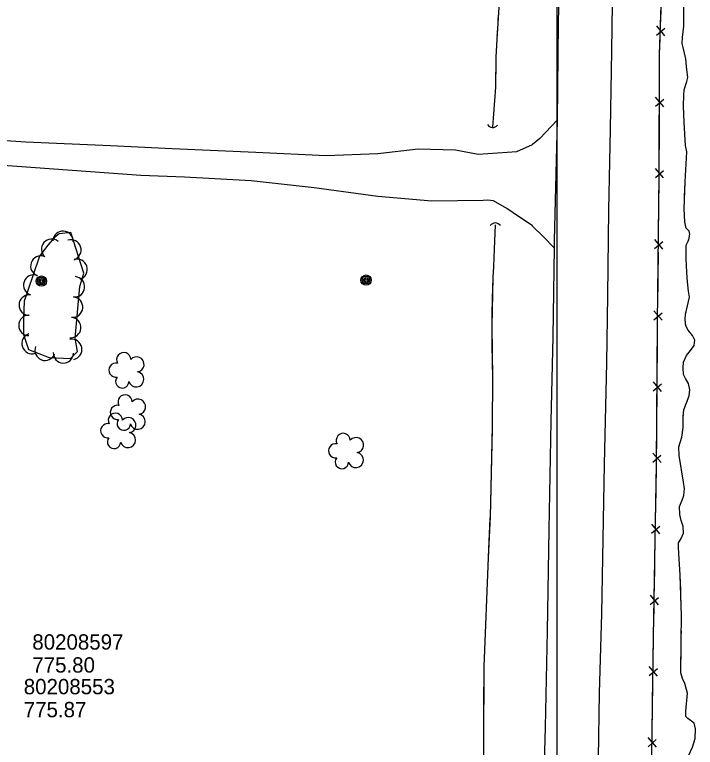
# Model space of a CAD drawing. Extents: x 591954 to 597000, y 198576 to 213500.
# Drawn here: x 593787.5 to 594054.2, y 209035.1 to 209321.9 of the extents above; entities that cross this region are included whole.
import ezdxf

# ---------------------------------------------------------------- set-up
doc = ezdxf.new("R2010")
doc.units = 0
for name, color, linetype in [('Level 10', 7, 'Continuous'), ('Level 11', 7, 'Continuous'), ('Level 14', 7, 'Continuous'), ('Level 15', 7, 'Continuous'), ('Level 17', 7, 'Continuous'), ('Level 18', 7, 'Continuous'), ('Level 19', 7, 'Continuous'), ('Level 6', 7, 'Continuous')]:
    doc.layers.add(name, color=color, linetype=linetype)

msp = doc.modelspace()

# ---------------------------------------------------------------- linework, layer by layer
at = {"layer": 'Level 10'}
msp.add_line((594000, 208500), (594000, 210000), dxfattribs=at)
at = {"layer": 'Level 11'}
for points in [[(594020.92, 209277.11), (594021.48, 209307.69), (594021.88, 209335.45), (594022.61, 209371.28), (594023.09, 209403.36), (594023.94, 209439.53), (594024.67, 209469.56), (594025.38, 209501.65), (594026.16, 209533.36), (594026.37, 209550.34)], [(594004.19, 209515.2), (594003.26, 209463.8), (594002.68, 209437.72), (594002.04, 209402.73), (594001.04, 209348.37), (594000.39, 209318.67), (593999.97, 209280.6)], [(593999.97, 209280.6), (593998.9, 209233.41), (593998.85, 209230.64)], [(594009.01, 208631.52), (594009.27, 208667.78), (594010.66, 208721.83), (594011.4, 208782.36), (594012.13, 208808.26), (594012.62, 208840.15), (594013.04, 208868.19), (594013.68, 208893.39), (594014.42, 208925.71), (594015, 208950.25), (594015.72, 209004.45), (594016.24, 209030.86), (594016.62, 209056.33), (594017.53, 209087.3), (594018.52, 209145.92), (594019.42, 209185.52), (594019.83, 209212.01), (594020.29, 209245.3), (594020.92, 209277.11)], [(593998.85, 209230.64), (593998.3, 209195.94), (593997.61, 209162.68), (593996.73, 209120.37), (593996.08, 209080.6), (593995.31, 209042.89), (593994.35, 209005.26), (593994.1, 208967.53), (593993.55, 208932.78), (593992.64, 208890.84), (593992, 208857.63), (593991.15, 208818.04), (593990.48, 208781.03), (593989.3, 208741.66), (593988.74, 208713.42), (593988.39, 208682.48), (593987.81, 208648.94), (593987.57, 208630.06)]]:
    msp.add_lwpolyline(points, dxfattribs=at)
at = {"layer": 'Level 14'}
for centre, radius in [((593925.18, 209217.97), 2.02), ((593798.02, 209217.58), 2.02), ((593798.01, 209217.6), 1.52), ((593798.02, 209217.56), 1.01), ((593798.02, 209217.57), 0.502), ((593925.18, 209217.99), 1.52), ((593925.18, 209217.95), 1.01), ((593925.19, 209217.96), 0.502)]:
    msp.add_circle(centre, radius, dxfattribs=at)
at = {"layer": 'Level 15'}
for p, q in [((594038.92, 209313.91), (594042.18, 209316.6)), ((594042.15, 209313.64), (594039.03, 209317.46)), ((594041.83, 209285.83), (594038.61, 209289.56)), ((594038.6, 209286.01), (594041.78, 209288.8)), ((594038.49, 209258.15), (594041.68, 209260.93)), ((594041.73, 209257.97), (594038.51, 209261.7)), ((594038.2, 209230.3), (594041.4, 209233.07)), ((594041.43, 209230.1), (594038.23, 209233.85)), ((594041.14, 209202.24), (594037.94, 209205.99)), ((594037.9, 209202.45), (594041.1, 209205.21)), ((594037.69, 209174.58), (594040.88, 209177.35)), ((594040.92, 209174.39), (594037.71, 209178.13)), ((594037.47, 209146.72), (594040.67, 209149.49)), ((594040.71, 209146.53), (594037.5, 209150.27)), ((594036.99, 209118.88), (594040.21, 209121.62)), ((594040.23, 209118.65), (594037.05, 209122.43)), ((594036.5, 209091.03), (594039.72, 209093.77)), ((594039.74, 209090.8), (594036.56, 209094.57)), ((594036.06, 209063.16), (594039.27, 209065.91)), ((594039.29, 209062.95), (594036.11, 209066.71)), ((594035.65, 209035.31), (594038.86, 209038.06)), ((594038.89, 209035.09), (594035.7, 209038.86))]:
    msp.add_line(p, q, dxfattribs=at)
for points in [[(594030.79, 208634.01), (594031.94, 208683.98), (594033.37, 208764.41), (594034.53, 208848.11), (594035.64, 208920.32), (594036.5, 208979.5), (594037.1, 209031.73), (594037.78, 209078.39), (594038.97, 209145.83), (594039.39, 209201.19), (594040, 209259.04), (594040.17, 209306.37), (594041.42, 209344.67), (594041.5, 209389.61), (594042.2, 209438.38), (594043.44, 209486.71), (594045.27, 209558.54)], [(594040.59, 209319.11), (594040.96, 209330.43)], [(594040.16, 209302.58), (594040.17, 209306.37), (594040.37, 209312.53)], [(594040.12, 209291.26), (594040.16, 209302.58)], [(594040.06, 209274.72), (594040.09, 209284.68)], [(594040.01, 209263.4), (594040.06, 209274.72)], [(594039.87, 209246.86), (594039.97, 209256.82)], [(594039.75, 209235.54), (594039.87, 209246.86)], [(594039.58, 209219), (594039.68, 209228.96)], [(594039.46, 209207.68), (594039.58, 209219)], [(594039.31, 209191.14), (594039.39, 209201.1)], [(594039.23, 209179.82), (594039.31, 209191.14)], [(594039.1, 209163.28), (594039.18, 209173.24)], [(594039.01, 209151.96), (594039.1, 209163.28)], [(594038.78, 209135.43), (594038.96, 209145.38)], [(594038.58, 209124.11), (594038.78, 209135.43)], [(594038.29, 209107.57), (594038.47, 209117.52)], [(594038.09, 209096.25), (594038.29, 209107.57)], [(594037.8, 209079.71), (594037.98, 209089.67)], [(594037.63, 209068.39), (594037.78, 209078.39), (594037.8, 209079.71)], [(594037.39, 209051.86), (594037.54, 209061.81)], [(594037.23, 209040.54), (594037.39, 209051.86)]]:
    msp.add_lwpolyline(points, dxfattribs=at)
for centre, start, end in [((593974.76, 209280.23), 214.2082, 320.4478), ((593975.78, 209237.83), 36.8794, 143.119)]:
    msp.add_arc(centre, 2.5, start, end, dxfattribs=at)
at = {"layer": 'Level 17'}
for points in [[(593549.62, 209275.76), (593550.25, 209275.98), (593557.81, 209277.99), (593569.7, 209280.1), (593588.61, 209280.91), (593618.58, 209281.04), (593645.5, 209280.53), (593677.34, 209278.92), (593706.45, 209277.89), (593735.5, 209275.73), (593764.6, 209273.9), (593791.92, 209272.11), (593825.06, 209270.71), (593849.21, 209269.45), (593881.95, 209268.09), (593909.58, 209266.77), (593929.73, 209267.52), (593945.57, 209269.4), (593960.22, 209268.99), (593969.04, 209267.32), (593984.2, 209268.32), (593990.43, 209271.07)], [(593999.97, 209280.61), (593993.2, 209273.43), (593990.43, 209271.07)], [(593990.32, 209239.2), (593982.82, 209244.3), (593980.33, 209246.04), (593975.05, 209249.06), (593972.79, 209249.31), (593971.01, 209249.16), (593950.93, 209248.82), (593929.84, 209250.72), (593904.86, 209254.13), (593880.15, 209256.85), (593854.02, 209258.32), (593836.93, 209258.94), (593781.28, 209262.91)], [(593990.24, 209239.26), (593994.74, 209234.86), (593998.85, 209230.64)]]:
    msp.add_lwpolyline(points, dxfattribs=at)
at = {"layer": 'Level 18'}
for points in [[(593811.2, 209195.24), (593813.1, 209215.5), (593814.68, 209220.74), (593809.56, 209236.66), (593804.99, 209236.12), (593803.11, 209234.61), (593800.56, 209231.66), (593797.25, 209227.35), (593794.62, 209219.68)], [(593794.62, 209219.68), (593791.22, 209209.76), (593791.05, 209202.82), (593791.02, 209196.63), (593792.95, 209190.74), (593801.09, 209187.64), (593809.36, 209187.27), (593812.2, 209190.05), (593811.2, 209195.24)]]:
    msp.add_lwpolyline(points, dxfattribs=at)
for centre, radius, start, end in [((593793.13, 209200.24), 4, 89.7854, 269.77), ((593830.24, 209186.82), 2.78, 1.3946, 209.1675), ((593835.28, 209184.96), 2.97, 278.4237, 139.6575), ((593827.24, 209182.74), 2.78, 78.0716, 279.0826), ((593829.7, 209178.34), 2.61, 140.7797, 358.7123), ((593835.17, 209179.11), 2.97, 196.0745, 79.0477), ((593830.8, 209170.26), 2.78, 1.3946, 209.1675), ((593835.85, 209168.41), 2.97, 278.4237, 139.6575), ((593827.8, 209166.19), 2.78, 78.0716, 279.0826), ((593827, 209163.08), 2.78, 1.3946, 209.1675), ((593835.74, 209162.55), 2.97, 196.0745, 79.0477), ((593830.27, 209161.79), 2.61, 140.7797, 358.7123), ((593832.05, 209161.22), 2.97, 278.4237, 139.6575), ((593824, 209159), 2.78, 78.0716, 279.0826), ((593831.94, 209155.37), 2.97, 196.0745, 79.0477), ((593916.24, 209155.22), 2.78, 1.3946, 209.1675), ((593826.47, 209154.6), 2.61, 140.7797, 358.7123), ((593921.28, 209153.36), 2.97, 278.4237, 139.6575), ((593913.24, 209151.14), 2.78, 78.0716, 279.0826), ((593915.7, 209146.74), 2.61, 140.7797, 358.7123), ((593921.17, 209147.51), 2.97, 196.0745, 79.0477)]:
    msp.add_arc(centre, radius, start, end, dxfattribs=at)
for centre, major_axis, ratio, start_param, end_param in [((593806.52, 209233.14), (2.32, -3.26), 0.999966, 0.908479, 4.049804), ((593802.03, 209230.06), (-2.14, 3.38), 0.999911, 5.005545, 8.146871), ((593809.57, 209229.78), (1.94, -3.5), 0.999924, 6.087522, 9.228848), ((593797.8, 209223.48), (0.02, 4), 0.999965, 5.957736, 9.099061), ((593812.02, 209222.17), (1.94, -3.5), 0.999924, 6.087522, 9.228848), ((593795.03, 209216.03), (-3.25, 2.34), 0.999996, 5.006585, 8.14791), ((593810.98, 209215.34), (2.74, -2.91), 0.999886, 5.435544, 8.576869), ((593793.27, 209208.2), (-3.79, 1.29), 0.99999, 5.017169, 8.158494), ((593810.24, 209207.38), (2.74, -2.91), 0.999886, 5.435544, 8.576869), ((593809.49, 209199.41), (2.74, -2.91), 0.999886, 5.435544, 8.576869), ((593794.37, 209193.12), (-3.92, 0.78), 0.999993, 5.223973, 8.365298), ((593809.91, 209190.85), (-3.29, -2.27), 0.999991, 1.156889, 4.298215), ((593799.47, 209190.5), (-1.34, 3.77), 0.999995, 0.865661, 4.006987), ((593806.65, 209189.49), (-1.47, 3.72), 0.999992, 1.15025, 4.291576)]:
    msp.add_ellipse(centre, major_axis=major_axis, ratio=ratio, start_param=start_param, end_param=end_param, dxfattribs=at)
at = {"layer": 'Level 19'}
for p, q in [((593974.63, 209210.64), (593974.5, 209204.64)), ((593974.41, 209198.64), (593974.49, 209192.64)), ((593973.71, 209124.65), (593973.43, 209118.66)), ((593973.43, 209118.66), (593973.14, 209112.66)), ((593973.14, 209112.66), (593971.82, 209079.69)), ((593971.23, 209050.7), (593971.2, 209044.7)), ((593971.2, 209044.7), (593971.17, 209038.7)), ((593971.17, 209038.7), (593971.14, 209032.7))]:
    msp.add_line(p, q, dxfattribs=at)
for points in [[(593978.67, 209513.82), (593976.88, 209498.25), (593975.2, 209474.03), (593975.23, 209464.47), (593977.74, 209452.39), (593979.6, 209443.54), (593980.33, 209437.45), (593978.03, 209402.79), (593977.08, 209396.36), (593976.71, 209385.47), (593977.06, 209379.4), (593977.97, 209369.89), (593978.41, 209350.52), (593977.28, 209326.75), (593976.48, 209314.33), (593976.01, 209305.36), (593975.89, 209293.45), (593974.71, 209277.83)], [(594049.6, 209290.32), (594049.81, 209292.42), (594050.8, 209295.66), (594051.25, 209297.23), (594050.92, 209299.37), (594050.68, 209301.53), (594050.44, 209304.54), (594049.41, 209309.07), (594048.93, 209310.57), (594049.07, 209313.01), (594049.62, 209317.38), (594049.68, 209325.32)], [(593976.96, 209321.72), (593976.83, 209319.72)], [(594049.6, 209290.32), (594049.81, 209292.42), (594050.8, 209295.66), (594051.25, 209297.23), (594050.92, 209299.37), (594050.68, 209301.53), (594050.44, 209304.54), (594049.41, 209309.07), (594048.93, 209310.57), (594049.07, 209313.01), (594049.62, 209317.38), (594049.63, 209318.82)], [(593976.57, 209315.73), (593976.48, 209314.33), (593976.45, 209313.73)], [(593976.24, 209309.74), (593976.13, 209307.74)], [(593975.99, 209303.75), (593975.89, 209293.45), (593974.71, 209277.83)], [(594051.26, 209046.33), (594050.46, 209047.08), (594050.39, 209049.23), (594051.02, 209056.27), (594050.01, 209060.01), (594049.15, 209062.07), (594048.53, 209064.22), (594048.59, 209076.85), (594048.79, 209086.51), (594048.24, 209102.5), (594047.68, 209111), (594047.52, 209113.43), (594047.59, 209115.09), (594048.59, 209116.84), (594049.56, 209118.86), (594049.36, 209121.52), (594048.64, 209123.84), (594048.04, 209126.24), (594048, 209129.31), (594049.04, 209131.78), (594049.68, 209133.67), (594049.86, 209136.3), (594049.45, 209138.9), (594047.76, 209149.26), (594047.73, 209152.75), (594048.9, 209156.42), (594049.34, 209160.26), (594049.35, 209162.23), (594049.42, 209164.7), (594049.65, 209167.17), (594051.71, 209172.63), (594051.97, 209174.98), (594051.5, 209177.51), (594050.27, 209179.39), (594049.48, 209181.03), (594049.33, 209183.57), (594049.55, 209185.86), (594050.67, 209188.43), (594052.27, 209190.46), (594053.68, 209192.35), (594053.89, 209194.47), (594052.99, 209196.34), (594051.38, 209198.33), (594050.41, 209200.08), (594050.12, 209202.71), (594050.28, 209204.45), (594051.86, 209211.29), (594051.42, 209213.7), (594051.07, 209217.31), (594050.83, 209220.84), (594050.65, 209223.99), (594050.53, 209226), (594050.57, 209231.64), (594051.55, 209233.69), (594052.03, 209235.99), (594051.71, 209237.1), (594050.51, 209238.36), (594049.98, 209240.72), (594049.73, 209245.93), (594050.17, 209256.41), (594050.79, 209268.18), (594050.25, 209270.61), (594049.76, 209279.65), (594049.56, 209286.22), (594049.6, 209290.32)], [(594049.77, 209279.62), (594049.76, 209279.65), (594049.56, 209286.22), (594049.6, 209290.32)], [(594049.93, 209250.72), (594050.17, 209256.41), (594050.79, 209268.18), (594050.25, 209270.61), (594049.77, 209279.62)], [(594049.79, 209244.72), (594049.73, 209245.93), (594049.76, 209246.72)], [(594050.42, 209238.77), (594049.98, 209240.72), (594049.98, 209240.73)], [(593975.8, 209239.61), (593975.31, 209230.02), (593975.08, 209223.36), (593974.82, 209218.94), (593974.39, 209199.99), (593974.65, 209179.67), (593974.54, 209161.11), (593974.09, 209136.67), (593973.75, 209125.41), (593972.98, 209109.24), (593971.31, 209066.7), (593970.86, 208977.14), (593968.59, 208950.35), (593967.24, 208921.98), (593966.7, 208865.53), (593965.91, 208843.14), (593965.98, 208815.45), (593966.68, 208786.54), (593966.53, 208770.93), (593965.89, 208712.84), (593964.64, 208644.79), (593963.27, 208633.42), (593963.54, 208628.1)], [(593975.8, 209239.61), (593975.31, 209230.02), (593975.08, 209223.36), (593974.82, 209218.94), (593974.63, 209210.64)], [(594051.4, 209233.39), (594051.55, 209233.69), (594051.89, 209235.32)], [(594050.33, 209200.85), (594050.12, 209202.71), (594050.28, 209204.45), (594051.86, 209211.29), (594051.42, 209213.7), (594051.07, 209217.31), (594050.83, 209220.84), (594050.65, 209223.99), (594050.53, 209226), (594050.55, 209229.58)], [(593974.5, 209204.64), (593974.39, 209199.99), (593974.41, 209198.64)], [(594051.95, 209174.76), (594051.97, 209174.98), (594051.5, 209177.51), (594050.27, 209179.39), (594049.48, 209181.03), (594049.33, 209183.57), (594049.55, 209185.86), (594050.67, 209188.43), (594052.27, 209190.46), (594053.68, 209192.35), (594053.89, 209194.47), (594052.99, 209196.34), (594051.38, 209198.33), (594050.41, 209200.08), (594050.33, 209200.85)], [(593974.49, 209192.64), (593974.65, 209179.67), (593974.54, 209161.11), (593974.51, 209159.64)], [(594050.35, 209169.02), (594051.06, 209170.89)], [(594049.37, 209163.16), (594049.42, 209164.7), (594049.46, 209165.16)], [(593974.51, 209159.64), (593974.09, 209136.67), (593973.91, 209130.65)], [(594048.99, 209157.18), (594049.22, 209159.17)], [(594048.38, 209124.9), (594048.04, 209126.24), (594048, 209129.31), (594049.04, 209131.78), (594049.68, 209133.67), (594049.86, 209136.3), (594049.45, 209138.9), (594047.76, 209149.26), (594047.73, 209152.75), (594047.92, 209153.34)], [(593973.91, 209130.65), (593973.75, 209125.41), (593973.71, 209124.65)], [(594048.44, 209096.56), (594048.24, 209102.5), (594047.68, 209111), (594047.52, 209113.43), (594047.59, 209115.09), (594048.59, 209116.84), (594049.56, 209118.86), (594049.36, 209121.52), (594048.64, 209123.84), (594048.38, 209124.9)], [(594048.65, 209090.56), (594048.58, 209092.56)], [(594048.75, 209084.57), (594048.79, 209086.51), (594048.79, 209086.57)], [(593971.82, 209079.69), (593971.31, 209066.7), (593971.23, 209050.7)], [(594048.63, 209078.57), (594048.67, 209080.57)], [(594051.26, 209046.33), (594050.46, 209047.08), (594050.39, 209049.23), (594051.02, 209056.27), (594050.01, 209060.01), (594049.15, 209062.07), (594048.53, 209064.22), (594048.58, 209074.57)], [(594050.16, 209029.01), (594050.72, 209030.09), (594053.02, 209035.09), (594054.05, 209038.48), (594054.16, 209042.33), (594053.75, 209044.46), (594051.26, 209046.33)], [(594050.72, 209030.09), (594053.02, 209035.09), (594054.05, 209038.48), (594054.16, 209042.33), (594053.75, 209044.46), (594051.26, 209046.33)]]:
    msp.add_lwpolyline(points, dxfattribs=at)

# ---------------------------------------------------------------- texts
at = {"layer": 'Level 6'}
for s, p in [('80208597', (593794.46, 209073.31)), ('775.80', (593794.46, 209064.31)), ('80208553', (593791.11, 209055.83)), ('775.87', (593791.11, 209046.83))]:
    msp.add_text(s, height=6, dxfattribs=at).set_placement(p)

doc.saveas('drawing.dxf')
